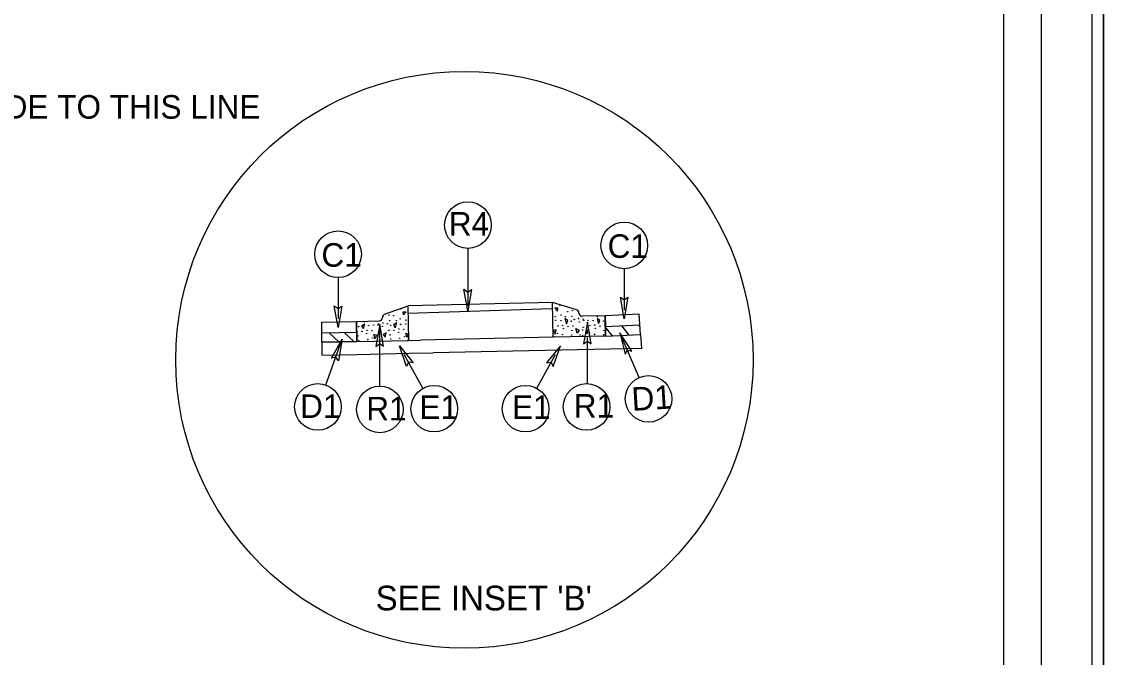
# Model space of a CAD drawing. Extents: x 2294455 to 2294795, y 719276 to 719941.
# Drawn here: x 2294722.8 to 2294794.5, y 719606.2 to 719648.3 of the extents above; entities that cross this region are included whole.
import ezdxf

# ---------------------------------------------------------------- set-up
doc = ezdxf.new("R2010")
doc.units = 0
for name, color, linetype in [('Default', 7, 'Continuous'), ('Old_Level_1', 7, 'Continuous'), ('Old_Level_11', 7, 'Continuous'), ('Sheet Plot Border Inside CELL', 7, 'Continuous'), ('Sheet Plot Border Outside CELL', 7, 'Continuous'), ('Sheet Typical CELL', 7, 'Continuous'), ('Typical Curb CELL', 7, 'Continuous'), ('Typical ID Circle CELL', 7, 'Continuous'), ('Typical Terminator CELL', 7, 'Continuous'), ('Typical Text ID Circle CELL', 7, 'Continuous')]:
    doc.layers.add(name, color=color, linetype=linetype)

msp = doc.modelspace()

# ---------------------------------------------------------------- linework, layer by layer
at = {"layer": 'Default'}
msp.add_lwpolyline([(2294454.524, 719715.329), (2294794.524, 719715.329), (2294794.524, 719495.329), (2294454.524, 719495.329)], close=True, dxfattribs=at)
at = {"layer": 'Old_Level_1'}
for p, q in [((2294758.014, 719629.715), (2294748.454, 719629.487)), ((2294758.003, 719629.283), (2294748.415, 719628.969)), ((2294761.505, 719628.827), (2294761.521, 719628.098)), ((2294763.847, 719627.578), (2294763.764, 719628.925)), ((2294742.733, 719627.069), (2294742.733, 719628.399)), ((2294761.51, 719628.092), (2294761.535, 719627.478)), ((2294761.988, 719627.497), (2294761.51, 719628.092)), ((2294761.521, 719628.098), (2294761.535, 719627.478)), ((2294763.103, 719627.546), (2294762.626, 719628.14)), ((2294763.815, 719628.097), (2294763.741, 719628.189)), ((2294743.849, 719627.09), (2294743.205, 719627.693)), ((2294744.196, 719627.711), (2294744.842, 719627.108)), ((2294745.035, 719627.692), (2294744.999, 719627.726)), ((2294745.034, 719627.727), (2294745.047, 719627.112)), ((2294758.064, 719627.402), (2294749.269, 719627.2)), ((2294761.535, 719627.478), (2294763.847, 719627.578)), ((2294761.535, 719627.478), (2294761.535, 719627.478)), ((2294763.847, 719627.578), (2294763.904, 719626.647)), ((2294745.047, 719627.112), (2294742.733, 719627.069)), ((2294742.733, 719627.069), (2294742.733, 719626.219)), ((2294745.047, 719627.112), (2294745.047, 719627.112)), ((2294763.904, 719626.647), (2294750.102, 719626.367))]:
    msp.add_line(p, q, dxfattribs=at)
for points in [[(2294763.764, 719628.925), (2294761.505, 719628.827)], [(2294742.733, 719628.399), (2294745.019, 719628.441)], [(2294763.809, 719628.192), (2294761.51, 719628.092)], [(2294742.733, 719627.684), (2294745.034, 719627.727)], [(2294742.733, 719627.069), (2294745.047, 719627.112), (2294748.502, 719627.184), (2294749.269, 719627.2)], [(2294742.733, 719626.219), (2294745.063, 719626.262), (2294748.52, 719626.334), (2294750.102, 719626.367)]]:
    msp.add_lwpolyline(points, dxfattribs=at)
at = {"layer": 'Old_Level_11'}
msp.add_circle((2294752.174, 719625.902), 19.133, dxfattribs=at)
at = {"layer": 'Sheet Plot Border Inside CELL'}
msp.add_lwpolyline([(2294790.424, 719710.839), (2294457.124, 719710.839), (2294457.124, 719499.819), (2294790.424, 719499.819)], close=True, dxfattribs=at)
at = {"layer": 'Sheet Plot Border Outside CELL'}
for points in [[(2294793.79, 719718.758), (2294456.99, 719718.758), (2294456.99, 719498.758), (2294793.79, 719498.758)], [(2294794.524, 719715.329), (2294454.524, 719715.329), (2294454.524, 719495.329), (2294794.524, 719495.329)]]:
    msp.add_lwpolyline(points, close=True, dxfattribs=at)
at = {"layer": 'Sheet Typical CELL'}
msp.add_lwpolyline([(2294787.924, 719710.329), (2294487.924, 719710.329), (2294487.924, 719500.329), (2294787.924, 719500.329)], close=True, dxfattribs=at)
at = {"layer": 'Typical Curb CELL'}
for p, q in [((2294746.885, 719628.928), (2294748.454, 719629.487)), ((2294748.502, 719627.184), (2294748.454, 719629.487)), ((2294758.064, 719627.402), (2294758.014, 719629.715)), ((2294759.612, 719629.221), (2294758.014, 719629.715)), ((2294746.742, 719628.707), (2294746.742, 719628.72)), ((2294748.123, 719629.085), (2294748.321, 719629.089)), ((2294748.139, 719628.887), (2294748.123, 719629.085)), ((2294748.321, 719629.089), (2294748.139, 719628.887)), ((2294758.363, 719629.325), (2294758.164, 719629.321)), ((2294758.164, 719629.321), (2294758.356, 719629.126)), ((2294758.356, 719629.126), (2294758.363, 719629.325)), ((2294759.765, 719629.006), (2294759.765, 719629.019)), ((2294761.505, 719628.827), (2294759.987, 719628.794)), ((2294761.505, 719628.827), (2294761.535, 719627.478)), ((2294761.535, 719627.478), (2294761.506, 719628.812)), ((2294745.019, 719628.455), (2294746.53, 719628.487)), ((2294745.019, 719628.455), (2294745.047, 719627.112)), ((2294745.047, 719627.112), (2294745.019, 719628.441)), ((2294745.378, 719628.159), (2294745.565, 719628.297)), ((2294745.476, 719627.953), (2294745.378, 719628.159)), ((2294745.565, 719628.297), (2294745.476, 719627.953)), ((2294747.495, 719628.239), (2294747.682, 719628.378)), ((2294747.593, 719628.031), (2294747.495, 719628.239)), ((2294747.682, 719628.378), (2294747.593, 719628.031)), ((2294758.836, 719628.635), (2294758.94, 719628.291)), ((2294759.029, 719628.504), (2294758.836, 719628.635)), ((2294758.94, 719628.291), (2294759.029, 719628.504)), ((2294760.964, 719628.645), (2294761.068, 719628.303)), ((2294761.157, 719628.514), (2294760.964, 719628.645)), ((2294761.068, 719628.303), (2294761.157, 719628.514)), ((2294746.173, 719627.582), (2294746.34, 719627.554)), ((2294746.261, 719627.301), (2294746.173, 719627.582)), ((2294746.34, 719627.554), (2294746.261, 719627.301)), ((2294746.987, 719627.697), (2294746.782, 719627.579)), ((2294746.782, 719627.579), (2294746.92, 719627.395)), ((2294746.92, 719627.395), (2294746.987, 719627.697)), ((2294748.29, 719627.663), (2294748.457, 719627.634)), ((2294748.378, 719627.382), (2294748.29, 719627.663)), ((2294748.457, 719627.634), (2294748.378, 719627.382)), ((2294761.535, 719627.478), (2294758.064, 719627.402)), ((2294758.257, 719627.891), (2294758.091, 719627.856)), ((2294758.091, 719627.856), (2294758.181, 719627.606)), ((2294758.181, 719627.606), (2294758.257, 719627.891)), ((2294759.563, 719627.982), (2294759.774, 719627.872)), ((2294759.643, 719627.681), (2294759.563, 719627.982)), ((2294759.774, 719627.872), (2294759.643, 719627.681)), ((2294760.385, 719627.901), (2294760.219, 719627.866)), ((2294760.219, 719627.866), (2294760.309, 719627.616)), ((2294760.309, 719627.616), (2294760.385, 719627.901)), ((2294745.047, 719627.112), (2294748.502, 719627.184))]:
    msp.add_line(p, q, dxfattribs=at)
for centre, radius in [((2294758.504, 719629.527), 0.0147), ((2294747.17, 719628.877), 0.0146), ((2294747.483, 719628.832), 0.0146), ((2294747.974, 719629.279), 0.0146), ((2294758.208, 719628.768), 0.0147), ((2294758.582, 719628.87), 0.0147), ((2294758.856, 719628.761), 0.0147), ((2294759.016, 719629.099), 0.0147), ((2294759.295, 719628.781), 0.0147), ((2294759.328, 719629.158), 0.0147), ((2294760.984, 719628.771), 0.0147), ((2294745.161, 719628.112), 0.0146), ((2294745.54, 719628.422), 0.0146), ((2294745.827, 719628.168), 0.0146), ((2294746.169, 719628.206), 0.0146), ((2294746.44, 719628.222), 0.0146), ((2294746.474, 719628.29), 0.0146), ((2294746.738, 719628.119), 0.0146), ((2294746.786, 719628.349), 0.0146), ((2294747.068, 719628.292), 0.0146), ((2294747.22, 719628.504), 0.0146), ((2294747.278, 719628.192), 0.0146), ((2294747.657, 719628.502), 0.0146), ((2294747.925, 719628.622), 0.0146), ((2294747.943, 719628.248), 0.0146), ((2294748.286, 719628.286), 0.0146), ((2294748.302, 719628.536), 0.0146), ((2294758.234, 719628.517), 0.0147), ((2294758.378, 719628.154), 0.0147), ((2294758.579, 719628.493), 0.0147), ((2294758.691, 719628.193), 0.0147), ((2294759.037, 719628.127), 0.0147), ((2294759.249, 719628.466), 0.0147), ((2294759.372, 719628.145), 0.0147), ((2294759.456, 719628.576), 0.0147), ((2294759.737, 719628.644), 0.0147), ((2294759.794, 719628.415), 0.0147), ((2294760.048, 719628.061), 0.0147), ((2294760.052, 719628.599), 0.0147), ((2294760.09, 719628.532), 0.0147), ((2294760.361, 719628.528), 0.0147), ((2294760.505, 719628.165), 0.0147), ((2294760.707, 719628.504), 0.0147), ((2294760.818, 719628.203), 0.0147), ((2294760.855, 719627.984), 0.0147), ((2294761.165, 719628.137), 0.0147), ((2294761.377, 719628.477), 0.0147), ((2294761.499, 719628.155), 0.0147), ((2294745.054, 719627.787), 0.0146), ((2294745.133, 719627.477), 0.0146), ((2294745.387, 719627.784), 0.0146), ((2294745.702, 719627.644), 0.0146), ((2294745.729, 719627.864), 0.0146), ((2294746.042, 719627.839), 0.0146), ((2294746.104, 719627.351), 0.0146), ((2294746.501, 719627.755), 0.0146), ((2294746.542, 719627.573), 0.0146), ((2294747.17, 719627.867), 0.0146), ((2294747.25, 719627.557), 0.0146), ((2294747.287, 719627.277), 0.0146), ((2294747.503, 719627.864), 0.0146), ((2294747.819, 719627.725), 0.0146), ((2294747.845, 719627.944), 0.0146), ((2294747.89, 719627.33), 0.0146), ((2294748.159, 719627.919), 0.0146), ((2294748.221, 719627.431), 0.0146), ((2294758.336, 719627.662), 0.0147), ((2294758.673, 719627.575), 0.0147), ((2294758.727, 719627.974), 0.0147), ((2294759.28, 719627.547), 0.0147), ((2294759.305, 719627.83), 0.0147), ((2294759.845, 719627.548), 0.0147), ((2294760.015, 719627.876), 0.0147), ((2294760.023, 719627.521), 0.0147), ((2294760.464, 719627.672), 0.0147), ((2294760.8, 719627.585), 0.0147), ((2294761.408, 719627.557), 0.0147), ((2294761.433, 719627.84), 0.0147), ((2294745.17, 719627.196), 0.0146), ((2294745.773, 719627.25), 0.0146), ((2294746.549, 719627.219), 0.0146), ((2294746.725, 719627.254), 0.0146)]:
    msp.add_circle(centre, radius, dxfattribs=at)
for centre, radius, start, end in [((2294746.958, 719628.724), 0.216, 109.62683, 181.19188), ((2294759.548, 719629.014), 0.217, 1.25635, 72.8214), ((2294759.982, 719629.011), 0.217, 181.25635, 271.25635), ((2294746.526, 719628.703), 0.216, 271.19188, 1.19188), ((2294758.143, 719627.417), 0.0147, 28.2949, 155.49791), ((2294748.423, 719627.196), 0.0146, 26.95031, 154.15332)]:
    msp.add_arc(centre, radius, start, end, dxfattribs=at)
at = {"layer": 'Typical ID Circle CELL'}
for p, q in [((2294752.402, 719633.302), (2294752.402, 719629.51)), ((2294762.766, 719631.948), (2294762.766, 719629.202)), ((2294743.802, 719631.361), (2294743.802, 719628.615)), ((2294746.57, 719624.157), (2294746.57, 719628.236)), ((2294760.332, 719624.323), (2294760.332, 719627.386)), ((2294763.765, 719624.732), (2294762.487, 719627.689)), ((2294742.99, 719624.234), (2294744.084, 719627.265)), ((2294749.429, 719624.013), (2294748.193, 719626.251)), ((2294756.976, 719624.013), (2294758.213, 719626.251))]:
    msp.add_line(p, q, dxfattribs=at)
for centre in [(2294752.407, 719634.842), (2294743.802, 719632.906), (2294762.767, 719633.493), (2294764.378, 719623.314), (2294742.466, 719622.781), (2294746.571, 719622.613), (2294750.176, 719622.661), (2294756.23, 719622.661), (2294760.27, 719622.779)]:
    msp.add_circle(centre, 1.545, dxfattribs=at)
at = {"layer": 'Typical Terminator CELL'}
for points in [[(2294752.648, 719630.576), (2294752.402, 719629.146), (2294752.147, 719630.584), (2294752.402, 719630.401)], [(2294744.048, 719629.471), (2294743.802, 719628.041), (2294743.547, 719629.479), (2294743.802, 719629.296)], [(2294763.013, 719630.059), (2294762.766, 719628.628), (2294762.512, 719630.067), (2294762.766, 719629.884)], [(2294746.817, 719626.805), (2294746.57, 719628.236), (2294746.316, 719626.797), (2294746.57, 719626.98)], [(2294760.572, 719626.97), (2294760.326, 719628.4), (2294760.072, 719626.962), (2294760.326, 719627.145)], [(2294763.28, 719626.474), (2294762.487, 719627.689), (2294762.824, 719626.268), (2294762.985, 719626.537)], [(2294743.367, 719626.003), (2294744.084, 719627.265), (2294743.835, 719625.825), (2294743.658, 719626.083)], [(2294748.344, 719625.469), (2294747.868, 719626.841), (2294748.786, 719625.704), (2294748.475, 719625.741)], [(2294758.062, 719625.469), (2294758.538, 719626.841), (2294757.62, 719625.704), (2294757.931, 719625.741)]]:
    msp.add_lwpolyline(points, close=True, dxfattribs=at)

# ---------------------------------------------------------------- texts
at = {"layer": 'Old_Level_1'}
msp.add_text("SEE INSET 'B'", height=1.63636, rotation=0, dxfattribs=at).set_placement((2294746.293, 719609.285))
at = {"layer": 'Old_Level_11'}
msp.add_text('GRADE TO THIS LINE', height=1.5625, rotation=359.99996, dxfattribs=at).set_placement((2294717.177, 719641.899))
at = {"layer": 'Typical Text ID Circle CELL'}
for s, p in [('R4', (2294751.139, 719634.147)), ('C1', (2294761.666, 719632.665)), ('C1', (2294742.701, 719632.078)), ('D1', (2294741.291, 719622.046)), ('R1', (2294745.67, 719621.885)), ('E1', (2294749.196, 719621.983)), ('E1', (2294755.335, 719621.983)), ('R1', (2294759.423, 719622.07))]:
    msp.add_text(s, height=1.5625, dxfattribs=at).set_placement(p)
msp.add_text('D1', height=1.5625, rotation=3.53228, dxfattribs=at).set_placement((2294763.302, 719622.512))

doc.saveas('drawing.dxf')
